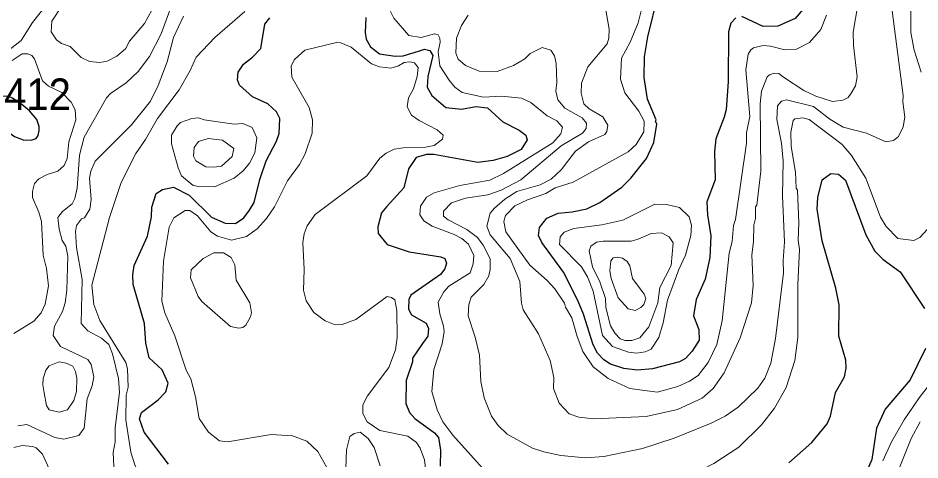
# Model space of a CAD drawing. Extents: x 673.6 to 698.9, y 7012 to 7040.1.
# Drawn here: x 676.673 to 678.962, y 7035.607 to 7036.731 of the extents above; entities that cross this region are included whole.
import ezdxf

# ---------------------------------------------------------------- set-up
doc = ezdxf.new("R2010")
doc.units = 0
doc.header["$LTSCALE"] = 0.032
doc.layers.add('1', color=7, linetype='Continuous', lineweight=25)
doc.layers.add('2', color=7, linetype='Continuous', lineweight=13)
doc.layers.add('21', color=7, linetype='Continuous')

msp = doc.modelspace()

# ---------------------------------------------------------------- linework, layer by layer
at = {"layer": '1'}
for points in [[(677.9937, 7036.1776), (677.9967, 7036.198), (678.0151, 7036.2216), (678.044, 7036.2343), (678.0798, 7036.2376), (678.1163, 7036.246), (678.1501, 7036.2613), (678.2058, 7036.3003), (678.2288, 7036.3233), (678.2681, 7036.3735), (678.2868, 7036.4143), (678.2941, 7036.4612), (678.2913, 7036.4683), (678.293, 7036.4717), (678.2709, 7036.5242), (678.2623, 7036.5795), (678.2631, 7036.6316), (678.2713, 7036.6826), (678.2975, 7036.7906)], [(678.6652, 7036.7521), (678.6454, 7036.7293), (678.6016, 7036.7101), (678.5647, 7036.7093), (678.5103, 7036.7341)], [(677.0545, 7035.5967), (676.9929, 7035.6777), (676.9812, 7035.7121), (676.9864, 7035.7276), (677.0282, 7035.7604), (677.0478, 7035.7808), (677.054, 7035.8021), (677.0388, 7035.8363), (677.0055, 7035.867), (676.9976, 7035.9044), (676.9942, 7035.9541), (676.9654, 7036.0531), (676.9639, 7036.0778), (676.9679, 7036.1016), (677.0017, 7036.1764), (677.0114, 7036.2253), (677.0124, 7036.2499), (677.0237, 7036.2849), (677.0395, 7036.2947), (677.0671, 7036.3003), (677.1068, 7036.2803), (677.1641, 7036.2247), (677.1989, 7036.2089), (677.2251, 7036.2082), (677.2459, 7036.2228), (677.2601, 7036.2423), (677.272, 7036.2615), (677.2862, 7036.3198), (677.3029, 7036.3674), (677.3286, 7036.4173), (677.3353, 7036.4372), (677.3377, 7036.4756), (677.3292, 7036.4918), (677.3068, 7036.5126), (677.2683, 7036.53), (677.2346, 7036.5603), (677.2295, 7036.5737), (677.2312, 7036.5927), (677.2448, 7036.6136), (677.2679, 7036.6308), (677.289, 7036.6531), (677.2991, 7036.715), (677.3119, 7036.731)], [(677.5555, 7036.7315), (677.5539, 7036.6934), (677.5569, 7036.6768), (677.5674, 7036.6575), (677.5905, 7036.6394), (677.6303, 7036.6338), (677.6508, 7036.6346), (677.689, 7036.6461), (677.7048, 7036.6513), (677.7184, 7036.6482), (677.7257, 7036.6356), (677.7133, 7036.5819), (677.7117, 7036.5552), (677.7231, 7036.5336), (677.7589, 7036.503), (677.7987, 7036.499), (677.8346, 7036.5054), (677.8642, 7036.5023), (677.9034, 7036.4666), (677.945, 7036.4455), (677.9615, 7036.4328), (677.9653, 7036.4206), (677.9496, 7036.3961), (677.9146, 7036.3784), (677.8785, 7036.3684), (677.8402, 7036.3634), (677.7284, 7036.3838), (677.71, 7036.3838), (677.6835, 7036.3759), (677.664, 7036.3469), (677.6525, 7036.2988), (677.6084, 7036.2511), (677.5958, 7036.2354), (677.5859, 7036.1999), (677.587, 7036.1832), (677.6101, 7036.1553), (677.6656, 7036.1365), (677.7463, 7036.1232), (677.7561, 7036.1191)], [(678.4946, 7036.7309), (678.4825, 7036.7175), (678.4759, 7036.6953), (678.4758, 7036.5685), (678.47, 7036.4981), (678.4655, 7036.4785), (678.4441, 7036.4235), (678.4405, 7036.3913), (678.4421, 7036.3193), (678.4217, 7036.2635), (678.4232, 7036.2306), (678.4314, 7036.1769), (678.4291, 7036.1221), (678.4173, 7036.0667), (678.3939, 7036.0153), (678.3872, 7035.9733), (678.4011, 7035.939), (678.4019, 7035.9117), (678.3844, 7035.884), (678.367, 7035.8651), (678.3522, 7035.8571), (678.2834, 7035.8393), (678.2449, 7035.8358), (678.2104, 7035.84), (678.1766, 7035.8507), (678.1601, 7035.8615), (678.1435, 7035.8789), (678.1331, 7035.9002)], [(678.6293, 7035.6004), (678.6881, 7035.6519), (678.7271, 7035.699), (678.7354, 7035.7188), (678.7476, 7035.779), (678.7706, 7035.819), (678.7749, 7035.8407), (678.7739, 7035.8613), (678.7561, 7035.9221), (678.7569, 7036.0017), (678.7484, 7036.0437), (678.7142, 7036.1642), (678.7011, 7036.2446), (678.7027, 7036.2742), (678.714, 7036.3189), (678.7358, 7036.3357), (678.7552, 7036.3336), (678.7731, 7036.3182), (678.8253, 7036.1792), (678.848, 7036.1377), (678.8692, 7036.1169), (678.9124, 7036.0853), (678.9736, 7035.9923)], [(678.1331, 7035.9002), (678.1084, 7035.9775), (678.0939, 7036.013), (678.0571, 7036.0847), (678.0021, 7036.1603), (677.9937, 7036.1776)], [(677.7561, 7036.1191), (677.7603, 7036.1076), (677.7561, 7036.0929), (677.7449, 7036.0788), (677.6696, 7036.0261), (677.6648, 7036.0149)], [(677.6648, 7036.0149), (677.664, 7035.9907), (677.6714, 7035.9759), (677.7089, 7035.9546), (677.7145, 7035.9412), (677.7131, 7035.9221), (677.6995, 7035.9033), (677.6739, 7035.8658), (677.6738, 7035.8567), (677.6583, 7035.8095), (677.6575, 7035.7507), (677.6662, 7035.7283), (677.6798, 7035.7123), (677.7302, 7035.6766), (677.7398, 7035.6641), (677.7453, 7035.6324), (677.7446, 7035.5916)], [(678.9764, 7035.8904), (678.9375, 7035.8108), (678.8738, 7035.736), (678.8519, 7035.688), (678.8398, 7035.6087), (678.8236, 7035.5683), (678.8117, 7035.5478), (678.7514, 7035.4778), (678.731, 7035.429), (678.7196, 7035.4092), (678.6843, 7035.372), (678.6701, 7035.3517), (678.6599, 7035.3209), (678.6549, 7035.2799), (678.6476, 7035.2606), (678.6147, 7035.1994), (678.5974, 7035.0781), (678.5877, 7035.0374), (678.5636, 7034.993), (678.5342, 7034.9733), (678.5112, 7034.9653), (678.4319, 7034.95), (678.3905, 7034.9375), (678.3584, 7034.9096)]]:
    msp.add_lwpolyline(points, dxfattribs=at)
msp.add_lwpolyline([(676.6067, 7036.507), (676.6098, 7036.4906), (676.6178, 7036.4755), (676.6297, 7036.46), (676.643, 7036.4449), (676.6639, 7036.4294), (676.6856, 7036.4214), (676.7065, 7036.4201), (676.7184, 7036.4245), (676.7237, 7036.4316), (676.7264, 7036.4445), (676.7264, 7036.4551), (676.7206, 7036.4729), (676.7016, 7036.4951), (676.6825, 7036.5106), (676.659, 7036.527), (676.6493, 7036.531), (676.6342, 7036.5319), (676.6226, 7036.5283), (676.6098, 7036.5203), (676.608, 7036.5137)], close=True, dxfattribs=at)
at = {"layer": '2'}
for points in [[(678.9657, 7036.5931), (678.9476, 7036.649), (678.9394, 7036.6938), (678.9394, 7036.7642), (678.9367, 7036.7722), (678.9345, 7036.8255), (678.9446, 7036.8806), (678.9595, 7036.9076), (679.0003, 7036.9414)], [(676.9781, 7036.5945), (677.0062, 7036.6327), (677.0361, 7036.6905), (677.0803, 7036.8113), (677.0956, 7036.841), (677.1276, 7036.8643)], [(678.5399, 7036.1621), (678.5403, 7036.2037), (678.5449, 7036.2207), (678.545, 7036.2504), (678.5481, 7036.2552), (678.558, 7036.3413), (678.5565, 7036.5124), (678.5599, 7036.5444), (678.5743, 7036.5809), (678.5805, 7036.5864), (678.5922, 7036.5906), (678.6037, 7036.5895), (678.6162, 7036.5801), (678.6672, 7036.5462), (678.6981, 7036.5316), (678.7402, 7036.5183), (678.7663, 7036.522), (678.7797, 7036.5288), (678.7881, 7036.5392), (678.7987, 7036.5586), (678.8029, 7036.5812), (678.7938, 7036.6609), (678.7931, 7036.6944), (678.8243, 7036.8791)], [(676.7489, 7036.8354), (676.7568, 7036.7997), (676.7558, 7036.7871), (676.7482, 7036.7687), (676.7095, 7036.7189), (676.6809, 7036.6737)], [(678.8835, 7036.8153), (678.9196, 7036.5339), (678.9188, 7036.5173), (678.9237, 7036.4784), (678.9196, 7036.4538), (678.9081, 7036.4292), (678.8949, 7036.4193), (678.8753, 7036.416), (678.8268, 7036.4377), (678.7678, 7036.4533), (678.7332, 7036.4731), (678.6919, 7036.5057), (678.6238, 7036.5227), (678.6107, 7036.5194), (678.601, 7036.5074), (678.5992, 7036.4729), (678.6106, 7036.4123), (678.6155, 7036.3673), (678.613, 7036.2784), (678.6181, 7036.1616), (678.6147, 7036.1146), (678.6163, 7036.0827), (678.5957, 7035.9157), (678.5842, 7035.8535), (678.5689, 7035.8148), (678.5506, 7035.7897), (678.5011, 7035.7417), (678.4675, 7035.7186), (678.4325, 7035.7006)], [(677.0221, 7036.7677), (676.9936, 7036.717), (676.9558, 7036.6718), (676.9455, 7036.6524), (676.9238, 7036.6334), (676.8991, 7036.6211), (676.8805, 7036.6173), (676.8541, 7036.6205), (676.8333, 7036.6306), (676.8053, 7036.6581), (676.7828, 7036.6656), (676.7704, 7036.6751), (676.7568, 7036.6951), (676.759, 7036.7226), (676.7845, 7036.7624)], [(677.6124, 7036.7591), (677.6269, 7036.7301), (677.6649, 7036.6864), (677.6963, 7036.6813), (677.7298, 7036.6905), (677.7393, 7036.688), (677.7435, 7036.6796), (677.7445, 7036.6695), (677.7396, 7036.6446), (677.7435, 7036.6089), (677.7673, 7036.5723), (677.7812, 7036.5549), (677.8006, 7036.5409), (677.8543, 7036.5294), (677.8998, 7036.5317), (677.9512, 7036.5269), (677.9743, 7036.5155), (678.0162, 7036.4824), (678.0403, 7036.4693), (678.055, 7036.4528), (678.0511, 7036.4359), (678.0306, 7036.4136), (677.905, 7036.3351), (677.8707, 7036.3181), (677.7942, 7036.305), (677.7294, 7036.286), (677.7101, 7036.2754), (677.6942, 7036.2527), (677.6929, 7036.2301), (677.7025, 7036.2149), (677.7238, 7036.2019), (677.7801, 7036.1806), (677.7993, 7036.1702), (677.8167, 7036.1554), (677.8299, 7036.127), (677.8284, 7036.1057), (677.8203, 7036.0827), (677.7661, 7036.0488), (677.7539, 7036.0343), (677.7396, 7036.0084), (677.7434, 7035.9783), (677.7531, 7035.9476), (677.7543, 7035.9337), (677.7497, 7035.9027), (677.7284, 7035.837), (677.7232, 7035.7815), (677.7366, 7035.7348), (677.7513, 7035.704), (677.7763, 7035.67), (677.8746, 7035.5609)], [(678.1637, 7036.7558), (678.1734, 7036.7023), (678.1727, 7036.6797), (678.1687, 7036.6649), (678.1191, 7036.6063), (678.103, 7036.5646), (678.102, 7036.5397), (678.1091, 7036.5124), (678.123, 7036.4994), (678.1577, 7036.4791), (678.1701, 7036.4583), (678.1677, 7036.4422), (678.1624, 7036.4348), (678.1209, 7036.4159), (678.0881, 7036.392), (678.0516, 7036.345), (678.0265, 7036.3211), (677.9983, 7036.3069), (677.9391, 7036.2893), (677.9082, 7036.2701), (677.8819, 7036.2475), (677.8711, 7036.2342), (677.863, 7036.2018), (677.8709, 7036.1796), (677.9218, 7036.1195), (677.9466, 7036.0609), (677.9506, 7036.0062), (677.9552, 7035.9891), (677.9943, 7035.9278), (678.024, 7035.8601), (678.0328, 7035.8168), (678.0323, 7035.7888), (678.0463, 7035.7515), (678.0722, 7035.7246), (678.0964, 7035.7158), (678.1344, 7035.7117), (678.2676, 7035.718), (678.3467, 7035.7358), (678.4098, 7035.7642), (678.4378, 7035.7887), (678.4656, 7035.8285)], [(678.0355, 7036.0421), (678.0163, 7036.0636), (677.9717, 7036.1025), (677.9107, 7036.1872), (677.9064, 7036.2135), (677.9103, 7036.2288), (677.9336, 7036.2531), (677.9659, 7036.2687), (678.0129, 7036.2848), (678.0367, 7036.2991), (678.0824, 7036.3137), (678.2217, 7036.3901), (678.2422, 7036.4091), (678.2614, 7036.4413), (678.2621, 7036.4684), (678.2486, 7036.4938), (678.2131, 7036.5405), (678.2023, 7036.5753), (678.2048, 7036.6285), (678.2268, 7036.669), (678.2473, 7036.718), (678.2556, 7036.7525)], [(677.0929, 7036.7349), (677.0676, 7036.6812), (677.0516, 7036.6194), (677.0289, 7036.5592), (677.0093, 7036.519), (676.961, 7036.4592), (676.8688, 7036.367), (676.8573, 7036.341), (676.8546, 7036.3239)], [(677.0854, 7035.3757), (677.0853, 7035.4131), (677.0712, 7035.44), (676.9906, 7035.5508), (676.9691, 7035.5946), (676.9589, 7035.6274), (676.9461, 7035.7094), (676.9475, 7035.7717), (676.9523, 7035.7927), (676.9508, 7035.8387), (676.9464, 7035.8548), (676.8806, 7035.9614), (676.8652, 7036.0021), (676.8603, 7036.0512), (676.905, 7036.2232), (676.935, 7036.3124), (676.9722, 7036.3866), (676.9962, 7036.4215), (677.0266, 7036.4754), (677.082, 7036.5483), (677.1101, 7036.5968), (677.1246, 7036.6308), (677.1725, 7036.6813), (677.2484, 7036.7475)], [(678.0511, 7035.6189), (678.0077, 7035.6278), (677.979, 7035.6373), (677.9141, 7035.6725), (677.8912, 7035.695), (677.8748, 7035.7185), (677.8562, 7035.7655), (677.8476, 7035.8066), (677.8446, 7035.8736), (677.8333, 7035.9193), (677.8152, 7035.9739), (677.8169, 7036.0021), (677.8228, 7036.0207), (677.8552, 7036.0533), (677.8676, 7036.0754), (677.8717, 7036.0918), (677.8709, 7036.1183), (677.8539, 7036.153), (677.839, 7036.1727), (677.8117, 7036.1928), (677.7644, 7036.2175), (677.7532, 7036.2272), (677.7528, 7036.2395), (677.7733, 7036.2605), (677.8086, 7036.2728), (677.8652, 7036.2814), (677.8993, 7036.2928), (677.9489, 7036.3192), (678.0518, 7036.406), (678.1061, 7036.4382), (678.1152, 7036.4499), (678.1159, 7036.4632), (678.1049, 7036.477), (678.0609, 7036.5018), (678.0427, 7036.5226), (678.0379, 7036.5447), (678.0404, 7036.5667), (678.0387, 7036.6148), (678.0345, 7036.6345), (678.0253, 7036.6489), (678.0029, 7036.6558), (677.9729, 7036.6404), (677.9594, 7036.6272), (677.9304, 7036.6095), (677.8894, 7036.5943), (677.8431, 7036.5951), (677.809, 7036.6097), (677.7902, 7036.6261), (677.784, 7036.6415), (677.7856, 7036.6793), (677.7987, 7036.7117), (677.8154, 7036.7375)], [(678.7248, 7036.738), (678.7107, 7036.7017), (678.6821, 7036.6683), (678.6491, 7036.6515), (678.6192, 7036.6497), (678.5827, 7036.6591), (678.5639, 7036.6608), (678.54, 7036.655), (678.5327, 7036.6501), (678.5259, 7036.639), (678.5203, 7036.5989), (678.5301, 7036.48), (678.522, 7036.4389), (678.5219, 7036.4127), (678.4939, 7036.2187), (678.4892, 7036.203), (678.4857, 7036.1624), (678.4776, 7036.1332), (678.4602, 7035.9607), (678.4464, 7035.9006), (678.4245, 7035.8549), (678.3991, 7035.8224), (678.3775, 7035.808), (678.3476, 7035.7944), (678.2954, 7035.7792), (678.2257, 7035.7891), (678.1709, 7035.8146), (678.1331, 7035.8444), (678.1062, 7035.8831)], [(676.6809, 7036.6737), (676.615, 7036.6224)], [(677.729, 7036.4067), (677.7506, 7036.423), (677.7516, 7036.4325), (677.7366, 7036.4467), (677.6908, 7036.47), (677.6717, 7036.4834), (677.6603, 7036.5051), (677.6638, 7036.5274), (677.6771, 7036.5508), (677.6861, 7036.5816), (677.6885, 7036.6049), (677.6795, 7036.617), (677.6676, 7036.6196), (677.6528, 7036.6172), (677.6389, 7036.6092), (677.6194, 7036.6033), (677.5904, 7036.6061), (677.5698, 7036.6143), (677.5182, 7036.6561), (677.4923, 7036.6675), (677.4816, 7036.6681), (677.4007, 7036.649), (677.3748, 7036.6254), (677.3665, 7036.609), (677.3682, 7036.5804), (677.4115, 7036.5033), (677.4207, 7036.4718), (677.4192, 7036.4381), (677.4018, 7036.3852), (677.3876, 7036.3581), (677.3571, 7036.3164), (677.3241, 7036.2506), (677.3034, 7036.221), (677.2799, 7036.1946), (677.2529, 7036.1754), (677.2147, 7036.1663), (677.1791, 7036.1759), (677.1621, 7036.1873), (677.1282, 7036.2276), (677.1091, 7036.2417), (677.0967, 7036.2415), (677.0683, 7036.2229), (677.0567, 7036.1992), (677.042, 7036.1126), (677.0379, 7036.0113), (677.0454, 7035.9809), (677.0705, 7035.9232), (677.0998, 7035.8352), (677.1115, 7035.8135), (677.1233, 7035.7681), (677.1324, 7035.7123), (677.1561, 7035.6781), (677.1845, 7035.6559), (677.2041, 7035.6534), (677.3152, 7035.6722), (677.3695, 7035.669), (677.4055, 7035.6549), (677.4339, 7035.6292), (677.4716, 7035.5613)], [(676.6582, 7036.623), (676.6831, 7036.6394), (676.6973, 7036.6394), (676.7077, 7036.6354), (676.715, 7036.6269), (676.7347, 7036.5713), (676.7505, 7036.5572), (676.7839, 7036.5415), (676.8078, 7036.5167), (676.8182, 7036.4976), (676.8192, 7036.472), (676.8019, 7036.4156), (676.7978, 7036.3737), (676.7895, 7036.356), (676.7735, 7036.3414), (676.7466, 7036.3328), (676.7254, 7036.3219), (676.7148, 7036.3098), (676.7092, 7036.2898), (676.7092, 7036.2741), (676.7254, 7036.2371), (676.7322, 7036.2131), (676.7363, 7036.128), (676.7452, 7036.0942), (676.7501, 7036.0498), (676.7419, 7036.0035), (676.7318, 7035.9816), (676.7125, 7035.9602), (676.6625, 7035.9286)], [(676.6724, 7035.6941), (676.6948, 7035.6977), (676.7659, 7035.6643), (676.7893, 7035.66), (676.8268, 7035.6692), (676.8405, 7035.6881), (676.8486, 7035.7623), (676.8609, 7035.7956), (676.8651, 7035.8186), (676.8587, 7035.8502), (676.8501, 7035.863), (676.7808, 7035.8955), (676.762, 7035.9235), (676.765, 7035.9471), (676.7854, 7035.985), (676.7928, 7036.0064), (676.797, 7036.0388), (676.7995, 7036.1255), (676.7938, 7036.1506), (676.7851, 7036.1653), (676.7769, 7036.1938), (676.7741, 7036.2233), (676.7858, 7036.2387), (676.8098, 7036.2587), (676.8166, 7036.2718), (676.8225, 7036.298), (676.8291, 7036.3818), (676.8407, 7036.4277), (676.8975, 7036.528), (676.9077, 7036.5389), (676.9473, 7036.5659), (676.9781, 7036.5945)], [(678.6223, 7035.7918), (678.6451, 7035.8605), (678.6524, 7035.9186), (678.6525, 7036.0532), (678.6566, 7036.1424), (678.6534, 7036.1658), (678.655, 7036.2095), (678.6517, 7036.2931), (678.6485, 7036.2981), (678.6468, 7036.3384), (678.6354, 7036.4041), (678.6344, 7036.4407), (678.6403, 7036.4698), (678.6447, 7036.4746), (678.6648, 7036.4767), (678.6813, 7036.4726), (678.7648, 7036.4088), (678.7889, 7036.3814), (678.8246, 7036.3233), (678.8625, 7036.2246), (678.8764, 7036.2007), (678.9064, 7036.1704), (678.9467, 7036.1653), (678.9618, 7036.1729), (678.9819, 7036.1936)], [(677.5914, 7036.3745), (677.6072, 7036.3875), (677.6275, 7036.3969), (677.6501, 7036.401), (677.7071, 7036.402), (677.729, 7036.4067)], [(677.7076, 7035.5792), (677.7042, 7035.6073), (677.6939, 7035.6375), (677.6846, 7035.6517), (677.6622, 7035.6675), (677.5913, 7035.6824), (677.5588, 7035.7044), (677.5477, 7035.725), (677.5477, 7035.7475), (677.56, 7035.77), (677.6144, 7035.8421), (677.6308, 7035.8871), (677.6352, 7035.9189), (677.6344, 7035.9874), (677.6293, 7036.014), (677.6206, 7036.0206), (677.6099, 7036.023), (677.5303, 7035.9646), (677.4955, 7035.9518), (677.4782, 7035.9509), (677.4526, 7035.9611), (677.4237, 7035.9824), (677.404, 7036.0114), (677.3978, 7036.0392), (677.3994, 7036.091), (677.3961, 7036.1599), (677.3993, 7036.1822), (677.4066, 7036.202), (677.427, 7036.2315), (677.5583, 7036.3294), (677.5914, 7036.3745)], [(676.8546, 7036.3239), (676.8587, 7036.2695), (676.855, 7036.2451), (676.8412, 7036.223), (676.8341, 7036.2203), (676.8208, 7036.2035)], [(676.8208, 7036.2035), (676.8187, 7036.188), (676.8209, 7036.1473), (676.8356, 7036.0658), (676.8332, 7035.9539), (676.85, 7035.9351), (676.8843, 7035.9167), (676.9037, 7035.9006), (676.9129, 7035.8768), (676.9276, 7035.8144), (676.9301, 7035.7792), (676.9195, 7035.6889), (676.9194, 7035.653), (676.9146, 7035.6265), (676.9172, 7035.5722)], [(678.4656, 7035.8285), (678.5061, 7035.9176), (678.535, 7036.0071), (678.5391, 7036.0508), (678.5359, 7036.1287), (678.5399, 7036.1621)], [(678.1062, 7035.8831), (678.092, 7035.9208), (678.079, 7035.9686), (678.0626, 7035.9953), (678.0598, 7036.006), (678.0355, 7036.0421)], [(678.8677, 7035.6052), (678.8899, 7035.653), (678.9219, 7035.7089), (678.9605, 7035.7648), (679.0373, 7035.864)], [(678.3751, 7035.5651), (678.4387, 7035.5986), (678.5024, 7035.6396), (678.56, 7035.6963), (678.5931, 7035.7386), (678.6223, 7035.7918)], [(678.4325, 7035.7006), (678.3383, 7035.6628), (678.2583, 7035.6367), (678.1598, 7035.6165), (678.1132, 7035.6123), (678.0511, 7035.6189)], [(678.8844, 7035.5221), (678.9403, 7035.662), (678.9625, 7035.7046)], [(677.5046, 7035.5863), (677.5063, 7035.6328), (677.5153, 7035.6672), (677.5263, 7035.6742), (677.5412, 7035.678), (677.5616, 7035.6619), (677.5771, 7035.6386), (677.5924, 7035.5925)], [(676.7563, 7035.5756), (676.7352, 7035.6224), (676.7187, 7035.638), (676.7099, 7035.6417), (676.6829, 7035.6443), (676.6618, 7035.6394)]]:
    msp.add_lwpolyline(points, dxfattribs=at)
for points in [[(677.2215, 7036.3237), (677.2443, 7036.3422), (677.2607, 7036.362), (677.2736, 7036.3881), (677.2793, 7036.4257), (677.2672, 7036.4526), (677.2436, 7036.4626), (677.2213, 7036.4604), (677.1457, 7036.4718), (677.1312, 7036.4767), (677.1137, 7036.4751), (677.0855, 7036.4652), (677.077, 7036.4567), (677.0626, 7036.4327), (677.0624, 7036.4106), (677.079, 7036.3499), (677.0879, 7036.3298), (677.117, 7036.305), (677.1316, 7036.302), (677.1712, 7036.3018)], [(677.1889, 7036.3544), (677.2164, 7036.3784), (677.2206, 7036.3989), (677.192, 7036.4198), (677.1556, 7036.4241), (677.1309, 7036.4168), (677.12, 7036.4011), (677.1184, 7036.3793), (677.124, 7036.3679), (677.1498, 7036.3521), (677.1697, 7036.3511)], [(678.1564, 7035.9235), (678.1324, 7036.036), (678.1183, 7036.0727), (678.1034, 7036.0983), (678.047, 7036.155), (678.0489, 7036.1748), (678.0588, 7036.1867), (678.0835, 7036.1954), (678.1545, 7036.2052), (678.2084, 7036.2172), (678.2894, 7036.2574), (678.3187, 7036.2566), (678.3518, 7036.2489), (678.3766, 7036.2256), (678.3821, 7036.2043), (678.3805, 7036.1777), (678.3673, 7036.128), (678.35, 7036.0918), (678.3212, 7036.0135), (678.3106, 7035.9558), (678.2994, 7035.9184), (678.2803, 7035.8893), (678.265, 7035.8818), (678.2432, 7035.8789), (678.2224, 7035.881), (678.1815, 7035.896)], [(678.2312, 7035.9106), (678.2513, 7035.9179), (678.2739, 7035.9454), (678.2967, 7036.0071), (678.3017, 7036.0453), (678.3312, 7036.1016), (678.3361, 7036.1592), (678.3256, 7036.1742), (678.3066, 7036.185), (678.28, 7036.1832), (678.2474, 7036.1683), (678.2296, 7036.1637), (678.1583, 7036.1636), (678.1413, 7036.1605), (678.1267, 7036.1511), (678.1227, 7036.1391), (678.1313, 7036.0978), (678.1493, 7036.0599), (678.1637, 7036.0179), (678.1653, 7035.9944), (678.177, 7035.9482), (678.1887, 7035.9288), (678.2014, 7035.9153), (678.2142, 7035.9107)], [(677.2632, 7035.9707), (677.2654, 7035.9811), (677.2611, 7036.007), (677.2269, 7036.0647), (677.2235, 7036.1033), (677.2136, 7036.1217), (677.194, 7036.134), (677.17, 7036.1334), (677.1424, 7036.1197), (677.1124, 7036.0907), (677.1102, 7036.0705), (677.1299, 7036.0232), (677.1394, 7036.0103), (677.2121, 7035.9468), (677.2329, 7035.9427), (677.2435, 7035.9441), (677.2514, 7035.9503)], [(678.1965, 7036.0194), (678.1786, 7036.0688), (678.1752, 7036.0882), (678.1775, 7036.1132), (678.1836, 7036.1212), (678.1937, 7036.1231), (678.2076, 7036.1202), (678.2189, 7036.1121), (678.226, 7036.1008), (678.2326, 7036.0687), (678.2623, 7036.029), (678.2663, 7036.0175), (678.261, 7036.0026), (678.2541, 7035.9948), (678.239, 7035.9871), (678.2214, 7035.9916)], [(676.7362, 7035.8141), (676.7435, 7035.8355), (676.7519, 7035.8466), (676.7768, 7035.857), (676.7952, 7035.8536), (676.8118, 7035.8461), (676.8184, 7035.832), (676.8217, 7035.8153), (676.8208, 7035.7816), (676.8141, 7035.7582), (676.798, 7035.735), (676.7769, 7035.729), (676.7515, 7035.7343), (676.7451, 7035.7461), (676.7388, 7035.7776), (676.7356, 7035.7985)]]:
    msp.add_lwpolyline(points, close=True, dxfattribs=at)

# ---------------------------------------------------------------- texts
at = {"layer": '21', "width": 0.95}
msp.add_text('412', height=0.08, dxfattribs=at).set_placement((676.6375, 7036.497))

doc.saveas('drawing.dxf')
